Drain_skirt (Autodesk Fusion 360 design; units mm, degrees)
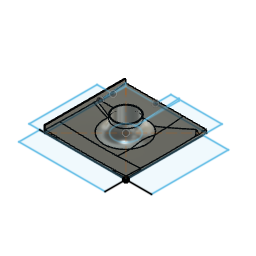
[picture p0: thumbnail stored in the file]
sketch "Sketch1" plane through (0, 0, 0) normal (0, 0, 1) x axis (1, 0, 0)
  line L1 (141.5078, 148.258) -> (-138.4922, 148.258)
  line L2 (141.5078, -131.742) -> (141.5078, 148.258)
  line L3 (-138.4922, -131.742) -> (141.5078, -131.742)
  line L4 (-138.4922, 148.258) -> (-138.4922, -131.742)
  line L5 (141.5078, -131.742) -> (-138.4922, 148.258)
  line L6 (-138.4922, -131.742) -> (141.5078, 148.258)
  circle C1 centre (1.5078, 8.258) radius 40
  point P6 (1.5078, 8.258)
  point P2 (-138.4922, 148.258)
  point P3 (141.5078, 148.258)
  point P5 (-138.4922, -131.742)
  horizontal L1
  vertical L2
  horizontal L3
  vertical L4
  midpoint L5 P6
  dimension "d1" distance P2 P3 = 280
  dimension "d2" distance P2 P5 = 280
  dimension "d3" diameter C1 = 80
extrude "Extrude1" new body sketch "Sketch1" profile of L1 L2 L3 L4 C1 along normal blind 3
sketch "Sketch2" plane through (0, 0, 3) normal (0, 0, 1) x axis (-1, 0, 0)
  line L1 (-141.5078, 131.742) -> (138.4922, 131.742)
  line L2 (-141.5078, -148.258) -> (-141.5078, 131.742)
  line L3 (138.4922, -148.258) -> (-141.5078, -148.258)
  line L4 (138.4922, 131.742) -> (138.4922, -148.258)
  circle C1 centre (-1.5078, -8.258) radius 40
  circle C2 centre (-1.5078, -8.258) radius 42.5
  concentric C1 C2
  dimension "d6" diameter C2 = 85
extrude "Extrude2" add sketch "Sketch2" profile of C1 C2 along normal blind 53
fillet "Fillet1" radius 40
sketch "Sketch3" plane through (0, 0, 0) normal (1, 0, 0) x axis (0, 1, 0)
  line L1 (193.9516, 10.2101) -> (193.9516, 3.2101)
  line L2 (42.1006, 2.2222) -> (193.9516, 10.2101)
  line L3 (193.9516, 3.2101) -> (42.1006, 2.2222)
  point P2 (193.9516, 3.2101)
  point P3 (193.9516, 10.2101)
  vertical L1
  dimension "d11" distance P2 P3 = 7
revolve "Revolve1" sketch "Sketch3" AlongAngle 290
sketch "Sketch4" plane through (0, 0, 0) normal (0, 1, 0) x axis (1, 0, 0)
sketch "Sketch5" plane through (0, 0, 0) normal (0, 0, -1) x axis (1, 0, 0)
  line L1 (-138.4922, 131.742) -> (141.5078, 131.742)
  line L2 (-138.4922, -148.258) -> (-138.4922, 131.742)
  line L3 (141.5078, -148.258) -> (-138.4922, -148.258)
  line L4 (141.5078, 131.742) -> (141.5078, -148.258)
  line L5 (-157.739, 131.742) -> (141.5078, 131.742)
  line L6 (-157.739, 204.034) -> (-157.739, 131.742)
  line L7 (141.5078, 204.034) -> (-157.739, 204.034)
  line L8 (141.5078, 131.742) -> (141.5078, 204.034)
  line L9 (-194.1224, -103.6604) -> (-138.4922, -103.6604)
  line L10 (-194.1224, 132.2311) -> (-194.1224, -103.6604)
  line L11 (-138.4922, 132.2311) -> (-194.1224, 132.2311)
  line L12 (-138.4922, -103.6604) -> (-138.4922, 132.2311)
  line L13 (230.1726, 131.742) -> (141.5078, 131.742)
  line L14 (230.1726, -135.5156) -> (230.1726, 131.742)
  line L15 (141.5078, -135.5156) -> (230.1726, -135.5156)
  line L16 (141.5078, 131.742) -> (141.5078, -135.5156)
  line L17 (141.3361, -202.0406) -> (-35.9274, -202.0406)
  line L18 (141.3361, -148.258) -> (141.3361, -202.0406)
  line L19 (-35.9274, -148.258) -> (141.3361, -148.258)
  line L20 (-35.9274, -202.0406) -> (-35.9274, -148.258)
  circle C1 centre (1.5078, -8.258) radius 40
  point P3 (141.5078, 131.742)
  point P7 (141.5078, 131.742)
  point P11 (-138.4922, -103.6604)
  point P21 (-35.9274, -148.258)
  horizontal L5
  vertical L6
  horizontal L7
  vertical L8
  coincident P3 P7
  horizontal L9
  vertical L10
  horizontal L11
  vertical L12
  coincident L2 P11
  horizontal L13
  vertical L14
  horizontal L15
  vertical L16
  horizontal L17
  vertical L18
  horizontal L19
  vertical L20
  coincident L3 P21
extrude "Extrude3" cut sketch "Sketch5" profile of L1 L2 L3 L4 L5 L6 L7 L8 L9 L10 L11 L12 L13 L14 L15 L16 L17 L18 L19 L20 against normal blind 40
sketch "Sketch6" plane through (0, 0, 3) normal (0, 0, 1) x axis (-1, 0, 0)
  line L1 (-141.5078, 131.742) -> (138.4922, 131.742)
  line L2 (-141.5078, -148.258) -> (-141.5078, 131.742)
  line L3 (138.4922, -148.258) -> (-141.5078, -148.258)
  line L4 (138.4922, 131.742) -> (138.4922, -148.258)
  line L5 (-125.6717, -148.258) -> (-141.5078, -148.258)
  line L6 (-141.5078, -148.258) -> (-141.5078, -133.2694)
  line L7 (-141.5078, -148.258) -> (-141.5078, -133.2694)
  line L8 (-141.5078, -133.2694) -> (-125.6717, -148.258)
  line L9 (-125.6717, -148.258) -> (-141.5078, -148.258)
  circle C1 centre (-1.5078, -8.258) radius 82.5
  point P4 (-141.5078, -148.258)
  point P7 (-141.5078, -148.258)
  point P8 (-125.6717, -148.258)
  point P9 (-141.5078, -133.2694)
  coincident P4 P7
  coincident L3 P8
  perpendicular L2 L5
  coincident L2 P9
  perpendicular L5 L6
extrude "Extrude4" add sketch "Sketch6" profile of L2 L3 L5 L6 L7 L8 L9 along normal blind 7.191
fillet "Fillet2" radius 18.5
fillet "Fillet3" radius 25
fillet "Fillet4" radius 20
sketch "Sketch7" plane through (-138.4922, 0, 0) normal (-1, 0, 0) x axis (0, -1, 0)
  curve K1 (-36.8122, 7.5457) -> (-50.4071, 2.9071)
  line L1 (-148.258, 3) -> (131.742, 3)
  line L2 (-148.258, 0) -> (-148.258, 3)
  line L3 (131.742, 0) -> (-148.258, 0)
  line L4 (131.742, 3) -> (131.742, 0)
  curve K2 (-50.4071, 2.9071) -> (131.742, 3.1918)
  line L5 (131.742, 10.0624) -> (131.742, 3.1918)
  curve K3 (131.742, 10.0624) -> (-36.8122, 7.5457)
  line L6 (-147.7232, 2.0001) -> (-147.7232, 10.9016)
  line L7 (-59.3023, 3) -> (-147.7232, 2.0001)
  line L8 (-59.3023, 3) -> (-147.7232, 10.9016)
  point P13 (-59.3023, 3)
  parallel L2 L6
  coincident L1 P13
extrude "Extrude5" add sketch "Sketch7" profile of L1 L6 L8 against normal blind 280
work_plane "WorkPlane1" AlongDistance -229
split "Split1"
work_plane "WorkPlane2" AlongDistance -200
work_plane "WorkPlane3" AlongDistance -200
split "Split2"
sketch "Sketch8" plane through (0, 0, 0) normal (0, 1, 0) x axis (1, 0, 0)
  line L1 (-142, -23) -> (-139, -23)
  line L2 (-142, 0) -> (-142, -23)
  line L3 (-139, 0) -> (-142, 0)
  line L4 (-139, -23) -> (-139, 0)
  horizontal L1
  vertical L2
  horizontal L3
  vertical L4
extrude "Extrude6" new body sketch "Sketch8" along normal blind 148 and against normal blind 132
sketch "Sketch9" plane through (-139, 0, 0) normal (1, 0, 0) x axis (0, 1, 0)
  line L1 (148, 0) -> (-132, 0)
  line L2 (148, 23) -> (148, 0)
  line L3 (-132, 23) -> (148, 23)
  line L4 (-132, 0) -> (-132, 23)
  circle C1 centre (53.6856, 7.7404) radius 6
  dimension "d34" diameter C1 = 12
extrude "Extrude8" cut sketch "Sketch9" profile of C1 against normal blind 4
sketch "Sketch11" plane through (-142, 0, 0) normal (-1, 0, 0) x axis (0, -1, 0)
  line L1 (-148, 23) -> (132, 23)
  line L2 (-148, 0) -> (-148, 23)
  line L3 (132, 0) -> (-148, 0)
  line L4 (132, 23) -> (132, 0)
  circle C1 centre (-53.6856, 7.7404) radius 6
  circle C2 centre (-53.6856, 7.7404) radius 6.3
  concentric C1 C2
  dimension "d37" diameter C2 = 12.6
work_plane "WorkPlane4" AlongDistance 10
sketch "Sketch12" plane through (-152, 8, 11.5) normal (-1, 0, 0) x axis (0, 1, 0)
  circle C1 centre (45.9035, 5.4054) radius 4.5
  dimension "d39" diameter C1 = 9
loft "Loft1" sketch "Sketch9" + "Sketch12"
shell "Shell1" innerThickness 1
sketch "Sketch13" plane through (-152, 8, 11.5) normal (-1, 0, 0) x axis (0, 1, 0)
sketch "Sketch14" plane through (-152, 0, 0) normal (-1, 0, 0) x axis (0, -1, 0)
  circle C1 centre (-53.9035, 6.0946) radius 4.5
  circle C2 centre (-53.9035, 6.0946) radius 4.8
  concentric C1 C2
  dimension "d41" diameter C2 = 9.6
extrude "Extrude9" add sketch "Sketch14" against normal blind 1.5
extrude "Extrude10" add sketch "Sketch9" profile of C1 against normal blind 3
sketch "Sketch15" plane through (-139, 0, 0) normal (1, 0, 0) x axis (0, 1, 0)
sketch "Sketch16" plane through (-139, 0, 0) normal (1, 0, 0) x axis (0, 1, 0)
  line L1 (50.5, 2.7698) -> (56.4774, 2.7698)
  line L2 (49.3983, 3.6238) -> (50.5, 2.7698)
  arc A1 centre (53.3696, 6.7753) radius 5.0698 clockwise from (49.3983, 3.6238) to (56.4774, 2.7698)
  horizontal L1
extrude "Extrude11" cut sketch "Sketch16" against normal blind 3
fillet "Fillet5" radius 1
fillet "Fillet6" radius 1 1
fillet "Fillet7" radius 1
sketch "Sketch18" plane through (0, 0, 0) normal (0, 0, -1) x axis (1, 0, 0)
sketch "Sketch19" plane through (-142, 0, 0) normal (-1, 0, 0) x axis (0, -1, 0)
  line L1 (-49.7483, 3.3525) -> (-49.3983, 3.6238)
  line L2 (-148, 23) -> (132, 23)
  line L3 (-148, 0) -> (-148, 23)
  line L4 (132, 0) -> (-148, 0)
  line L5 (132, 23) -> (132, 0)
  arc A1 centre (-53.7359, 7.3606) radius 5.6538 clockwise from (-49.7483, 3.3525) to (-48.7271, 4.738)
  arc A2 centre (-53.3696, 6.7753) radius 5.0698 clockwise from (-48.7271, 4.738) to (-49.3983, 3.6238)
  circle C1 centre (-53.7359, 7.3606) radius 6.1839
  concentric A1 C1
extrude "Extrude13" add sketch "Sketch19" profile of L1 A1 A2 C1 along normal blind 1
fillet "Fillet13" radius 0.5
fillet "Fillet14" radius 5.5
